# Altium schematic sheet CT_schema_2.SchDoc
size 276 x 169 mm
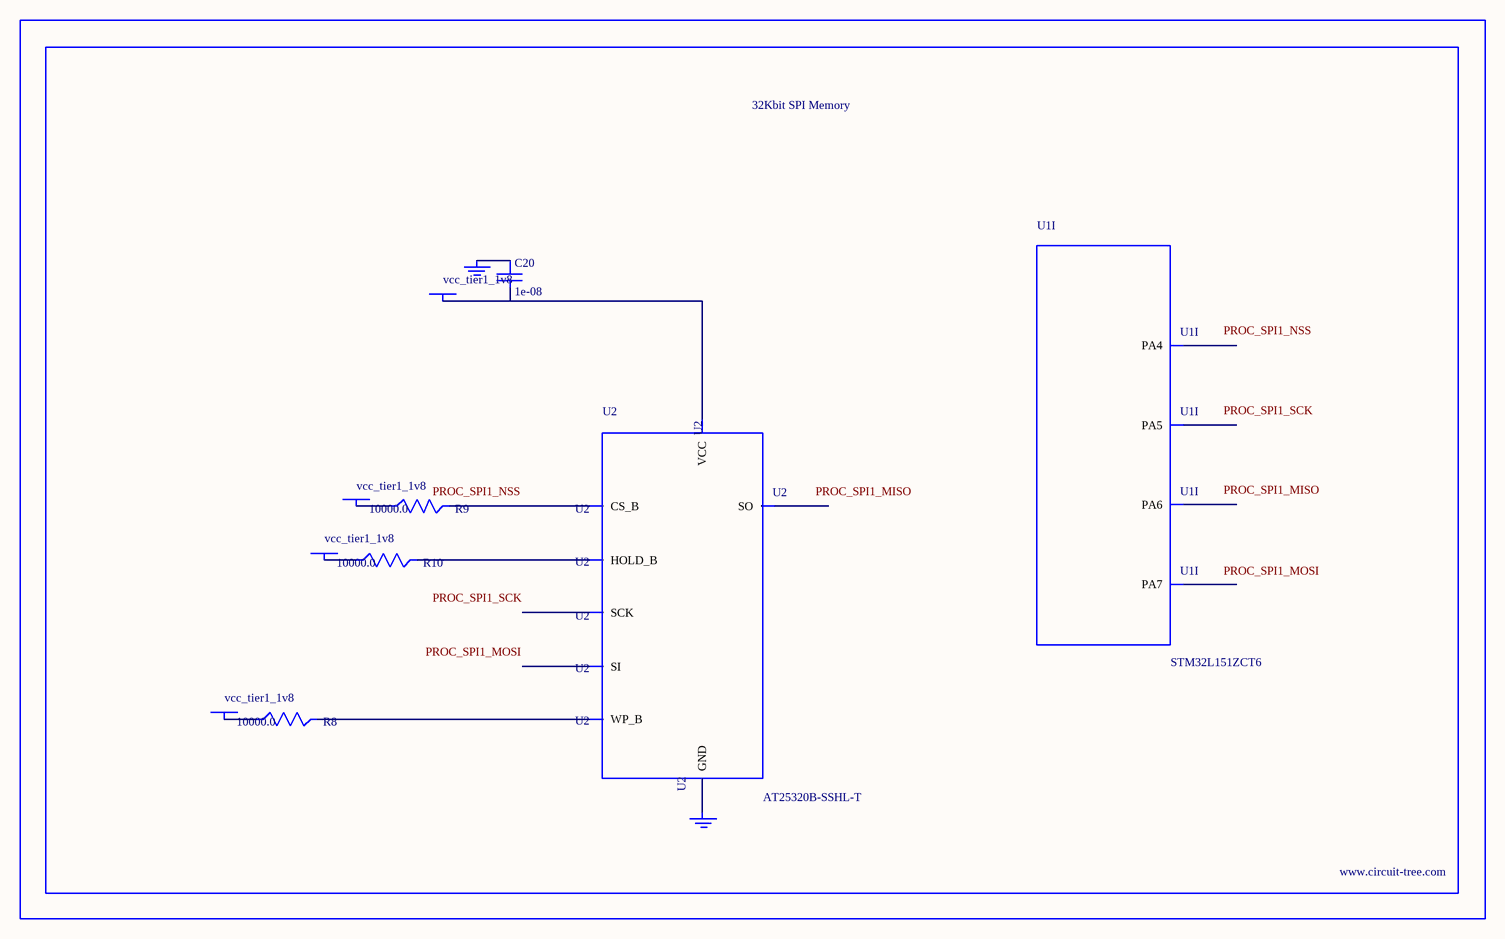
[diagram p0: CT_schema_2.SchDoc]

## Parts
BORDER1  (no value)
C20  1e-08  [C0402]
GND_INSTANCE_1_0  (no value)
GND_INSTANCE_1_1  (no value)
POWER_INSTANCE_1_0  vcc_tier1_1v8
POWER_INSTANCE_1_1  vcc_tier1_1v8
POWER_INSTANCE_1_2  vcc_tier1_1v8
POWER_INSTANCE_1_3  vcc_tier1_1v8
R8  10000.0  [R0603]
R9  10000.0  [R0603]
R10  10000.0  [R0603]
U1  STM32L151ZCT6  [LQFP144]  (part I of 11)
U2  AT25320B-SSHL-T  [SOIC-8]

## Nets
NetC20_1: C20.1 GND_INSTANCE_1_0.0(GND)
NetC20_2: C20.2 POWER_INSTANCE_1_3.0(PWR) U2.8(VCC)
NetGND_INSTANCE_1_1_0: GND_INSTANCE_1_1.0(GND) U2.4(GND)
NetPOWER_INSTANCE_1_0_0: POWER_INSTANCE_1_0.0(PWR) R9.1
NetPOWER_INSTANCE_1_1_0: POWER_INSTANCE_1_1.0(PWR) R8.1
NetPOWER_INSTANCE_1_2_0: POWER_INSTANCE_1_2.0(PWR) R10.1
NetR8_2: R8.2 U2.3(WP_B)
NetR9_2: R9.2 U2.1(CS_B)
NetR10_2: R10.2 U2.7(HOLD_B)

Not connected (* = marked no-connect by the designer): U1 40(PA4) 41(PA5) 42(PA6) 43(PA7); U2 2(SO) 5(SI) 6(SCK)

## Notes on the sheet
- Labels drawn without touching a wire or pin: PROC_SPI1_MISO, PROC_SPI1_MOSI, PROC_SPI1_NSS, PROC_SPI1_SCK

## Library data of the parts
BORDER1 = BORDER_PAGE1
C20 = C0402C103K3RAC
GND_INSTANCE_1_0 GND_INSTANCE_1_1 = GND
POWER_INSTANCE_1_0-POWER_INSTANCE_1_3 = PWR
R8-R10 = RC0603JR-0710KL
